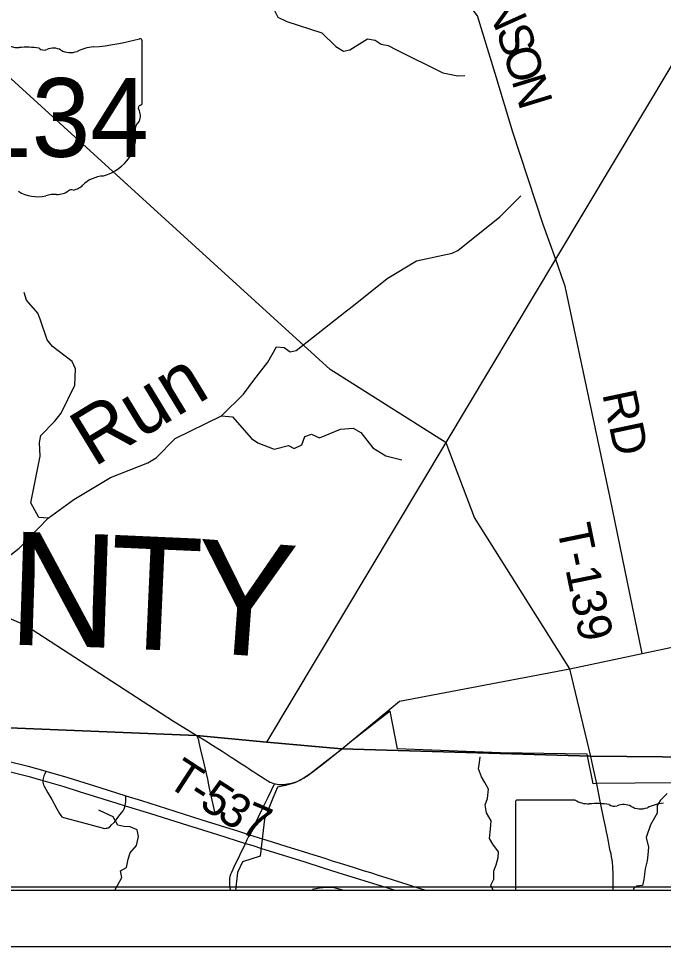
# Model space of a CAD drawing. Extents: x 0 to 34, y 0 to 22.
# Drawn here: x 4.521 to 5.601, y 14 to 15.554 of the extents above; entities that cross this region are included whole.
import ezdxf

# ---------------------------------------------------------------- set-up
doc = ezdxf.new("R2010")
doc.units = 0
for name, color, linetype in [('Default', 7, 'Continuous'), ('GM_X_City_Street', 7, 'Continuous'), ('GM_X_County_Text', 7, 'Continuous'), ('GM_X_Interchange_Ramps', 7, 'Continuous'), ('GM_X_Minor_Lake', 7, 'Continuous'), ('GM_X_Minor_River', 7, 'Continuous'), ('GM_X_Minor_River_Text', 7, 'Continuous'), ('GM_X_State_Location', 7, 'Continuous'), ('GM_X_State_Route', 7, 'Continuous'), ('GM_X_State_Shield', 7, 'Continuous'), ('GM_X_Township_Road', 7, 'Continuous'), ('GM_X_Township_Road_Text', 7, 'Continuous'), ('SH_Cut_Line', 7, 'Continuous'), ('SH_Data', 7, 'Continuous')]:
    doc.layers.add(name, color=color, linetype=linetype)

msp = doc.modelspace()

# ---------------------------------------------------------------- linework, layer by layer
at = {"layer": 'Default'}
msp.add_line((5.453, 14.2451), (5.3564, 14.2451), dxfattribs=at)
for points in [[(2.3212, 18.6531), (2.2797, 17.8302), (2.2668, 17.0936), (2.2632, 16.8811), (2.258, 16.7775), (2.1837, 15.746), (2.1, 14.637), (2.1, 14.4457), (2.4012, 14.4298), (2.4436, 14.4284), (2.5802, 14.4232), (3.783, 14.3901), (4.0144, 14.3862), (4.819, 14.3535), (4.9366, 14.3421), (5.2368, 14.8438), (5.4205, 15.1508), (5.9071, 15.964)], [(5.6182, 14.274), (5.4889, 14.273), (5.4832, 14.2724), (5.4732, 14.3218), (5.3279, 14.3242), (5.1554, 14.331), (5.1431, 14.394), (5.1265, 14.3811), (5.0756, 14.3413), (5.0632, 14.3309), (5.0346, 14.3087), (5.0087, 14.2887), (4.9974, 14.2812), (4.9836, 14.2742), (4.9678, 14.2695), (4.9546, 14.2665), (4.9467, 14.2481), (4.9329, 14.2132), (4.9257, 14.1511), (4.896, 14.1417), (4.8872, 14.1238), (4.8842, 14.0941), (5.6247, 14.0941)], [(5.3532, 14.2417), (5.3532, 14.0941), (5.6721, 14.0941)]]:
    msp.add_lwpolyline(points, dxfattribs=at)
msp.add_lwpolyline([(2.1, 14.4457), (2.1, 14.243), (2.102, 14.2411), (2.1319, 14.2168), (2.1359, 14.2103), (2.1425, 14.1753), (2.1455, 14.1482), (2.1436, 14.1288), (2.1399, 14.114), (2.1382, 14.1043), (2.1342, 14.0941), (7.3096, 14.0941), (7.3204, 14.3032), (6.8864, 14.3056), (6.7418, 14.3069), (5.4793, 14.3187), (5.0616, 14.3309), (4.9366, 14.3421), (4.819, 14.3535), (4.0144, 14.3862), (3.783, 14.3901), (2.5802, 14.4232), (2.4436, 14.4284), (2.4012, 14.4298)], close=True, dxfattribs=at)
for centre, major_axis, start_param, end_param in [((5.357, 14.2421), (0.00382, 0), 1.727492, 3.291633), ((5.476, 14.2684), (0.037, 0), 4.042888, 4.731792), ((5.4883, 14.1328), (0.133, 0), 1.404758, 1.657859), ((5.5184, 14.2432), (0.0107, 0), 3.836095, 5.185415), ((5.5341, 14.22), (0.0222, 0), 0.950623, 2.079405), ((5.61, 14.184), (0.0703, 0), 1.699012, 2.107814), ((5.5628, 14.2518), (0.0267, 0), 4.08156, 5.145723)]:
    msp.add_ellipse(centre, major_axis=major_axis, ratio=0.8, start_param=start_param, end_param=end_param, dxfattribs=at)
at = {"layer": 'GM_X_City_Street'}
msp.add_lwpolyline([(5.0132, 14.0962), (5.0156, 14.0967), (5.0247, 14.0981), (5.0364, 14.0991), (5.0438, 14.0992), (5.0486, 14.0987), (5.0558, 14.097), (5.0653, 14.0941)], dxfattribs=at)
at = {"layer": 'GM_X_Interchange_Ramps'}
msp.add_lwpolyline([(4.5664, 14.2935), (4.5651, 14.2902), (4.5632, 14.2856), (4.562, 14.2814), (4.5615, 14.278), (4.5613, 14.275), (4.5617, 14.2728), (4.5627, 14.2704), (4.5634, 14.2686), (4.5699, 14.2571), (4.5762, 14.246), (4.5851, 14.2303), (4.5894, 14.2228), (4.5914, 14.2193), (4.5932, 14.2173), (4.5958, 14.2162), (4.6256, 14.208), (4.6606, 14.1984), (4.6642, 14.1978), (4.6671, 14.1979), (4.6689, 14.1983), (4.6708, 14.1989), (4.6734, 14.2005), (4.6766, 14.2034), (4.6812, 14.2083), (4.6886, 14.2182), (4.6933, 14.224), (4.6958, 14.2273), (4.6976, 14.2306), (4.6993, 14.2356), (4.6998, 14.2386), (4.7002, 14.243), (4.7003, 14.2493), (4.7002, 14.2524)], dxfattribs=at)
at = {"layer": 'GM_X_Minor_Lake'}
msp.add_lwpolyline([(5.6072, 14.256), (5.5961, 14.2451), (5.5907, 14.2361), (5.5902, 14.2232), (5.5793, 14.2037), (5.5719, 14.1825), (5.5758, 14.1661), (5.5749, 14.1536), (5.574, 14.1434), (5.5701, 14.1298), (5.5683, 14.112), (5.5659, 14.1018), (5.5557, 14.1012), (5.5507, 14.0963), (5.5508, 14.0941)], dxfattribs=at)
at = {"layer": 'GM_X_Minor_River'}
for points in [[(4.8003, 15.6193), (4.8225, 15.6195), (4.8504, 15.6103), (4.8879, 15.5891), (4.9106, 15.5841), (4.9352, 15.5852), (4.9457, 15.5755), (4.9552, 15.5563), (4.9702, 15.5492), (5.029, 15.5299), (5.0521, 15.5071), (5.0652, 15.4993), (5.0759, 15.5017), (5.105, 15.5201), (5.1182, 15.518), (5.1283, 15.511), (5.1396, 15.5088), (5.1539, 15.5017), (5.2313, 15.4631), (5.2566, 15.4581), (5.2683, 15.4586)], [(4.5008, 14.6508), (4.5219, 14.6668), (4.5704, 14.7172), (4.6133, 14.7488), (4.6748, 14.7854), (4.7373, 14.8098), (4.7511, 14.8183), (4.7833, 14.8508), (4.8604, 14.8887), (4.8973, 14.9249), (4.9151, 14.9485), (4.9382, 14.9788), (4.9526, 15.004), (4.9655, 15.0031), (4.9756, 14.9961), (4.9855, 14.9978), (5.0698, 15.0647), (5.082, 15.0736), (5.1383, 15.1186), (5.1876, 15.1485), (5.2473, 15.1612), (5.2568, 15.1656), (5.327, 15.2222), (5.3619, 15.2569)], [(4.5704, 14.7172), (4.5545, 14.7186), (4.5412, 14.7431), (4.557, 14.821), (4.5558, 14.8438), (4.5582, 14.8559), (4.5809, 14.8794), (4.5921, 14.8929), (4.6147, 14.94), (4.6159, 14.9676), (4.6104, 14.9798), (4.5777, 15.0046), (4.5684, 15.0162), (4.5567, 15.0508), (4.5531, 15.0608), (4.534, 15.0823), (4.5301, 15.0952)], [(4.8604, 14.8887), (4.879, 14.8872), (4.9107, 14.8507), (4.9216, 14.8433), (4.9491, 14.8326), (4.9727, 14.8391), (4.9825, 14.834), (4.9954, 14.8402), (5.0005, 14.8538), (5.0112, 14.8582), (5.0248, 14.8519), (5.0598, 14.8665), (5.0814, 14.868), (5.0938, 14.8606), (5.114, 14.8353), (5.1361, 14.8216), (5.1629, 14.8151)], [(5.3159, 14.0941), (5.3121, 14.1024), (5.3168, 14.1125), (5.3166, 14.1266), (5.3209, 14.1367), (5.3241, 14.1492), (5.3246, 14.1587), (5.3153, 14.1714), (5.3094, 14.1809), (5.3115, 14.1965), (5.3124, 14.2105), (5.3047, 14.2235), (5.3026, 14.2372), (5.3061, 14.2478), (5.3078, 14.2633), (5.3019, 14.2748), (5.2964, 14.2843), (5.2913, 14.2977), (5.2929, 14.3079), (5.2938, 14.3174)], [(4.6822, 14.0941), (4.6862, 14.1022), (4.6936, 14.1157), (4.6914, 14.1264), (4.7017, 14.1323), (4.7045, 14.1459), (4.7077, 14.1565), (4.7184, 14.1688), (4.7217, 14.184), (4.7195, 14.1954), (4.7075, 14.2005), (4.6973, 14.2006), (4.6871, 14.2031), (4.6794, 14.2172), (4.6659, 14.2231), (4.655, 14.2282)]]:
    msp.add_lwpolyline(points, dxfattribs=at)
at = {"layer": 'GM_X_State_Route'}
msp.add_line((5.4796, 14.3182), (5.4443, 14.4648), dxfattribs=at)
for points in [[(5.4443, 14.4648), (5.2846, 14.7184), (5.2371, 14.8433), (5.0427, 14.9665), (4.4202, 15.5326), (4.3908, 15.5621)], [(5.4892, 14.2723), (5.4829, 14.3022), (5.4796, 14.3182)], [(4.4643, 14.3031), (4.5384, 14.2845), (4.5575, 14.2792), (4.5615, 14.278), (4.5963, 14.2678), (4.6224, 14.2597), (4.6852, 14.2399), (4.6993, 14.2356), (4.7398, 14.2232), (4.7949, 14.2057), (4.8542, 14.1872), (4.9008, 14.1726), (4.9129, 14.1688), (4.9275, 14.1641)], [(4.5025, 14.3105), (4.5368, 14.3017), (4.5649, 14.2939), (4.5664, 14.2935), (4.6031, 14.2827), (4.6571, 14.266), (4.7002, 14.2524), (4.7264, 14.2442), (4.7827, 14.2265), (4.8277, 14.2123), (4.8894, 14.1929), (4.9077, 14.1871), (4.9294, 14.1802)], [(5.5109, 14.1655), (5.5087, 14.176), (5.5071, 14.1846), (5.5056, 14.1919), (5.5037, 14.2009), (5.5012, 14.213), (5.4956, 14.2403), (5.4892, 14.2723)], [(4.9294, 14.1802), (4.9453, 14.1751), (4.9578, 14.1711), (4.9702, 14.1673), (4.9827, 14.1634), (4.9958, 14.1594), (5.0082, 14.1555), (5.0207, 14.1517), (5.0337, 14.1476), (5.0462, 14.1436), (5.0592, 14.1395), (5.0722, 14.1354), (5.0847, 14.1315), (5.0978, 14.1274), (5.1102, 14.1236), (5.1233, 14.1196), (5.1357, 14.1157), (5.1481, 14.1116), (5.1605, 14.1076), (5.173, 14.1036), (5.1848, 14.0999), (5.1967, 14.0961), (5.203, 14.0941)], [(4.9275, 14.1641), (4.9985, 14.142), (5.0311, 14.1317), (5.0553, 14.1239), (5.1444, 14.0963), (5.1512, 14.0941)], [(5.5167, 14.0941), (5.5167, 14.0958), (5.5168, 14.1009), (5.5168, 14.1064), (5.5168, 14.1141), (5.5166, 14.1206), (5.5166, 14.1252), (5.5163, 14.1291), (5.516, 14.1347), (5.5155, 14.1402), (5.5149, 14.1448), (5.5141, 14.15), (5.5132, 14.1549), (5.512, 14.1601), (5.5109, 14.1655)]]:
    msp.add_lwpolyline(points, dxfattribs=at)
at = {"layer": 'GM_X_State_Shield'}
for q in [(4.7276, 15.5168), (4.7276, 15.4121)]:
    msp.add_line((4.7276, 15.4121), q, dxfattribs=at)
for centre, major_axis, start_param, end_param in [((4.5208, 15.535), (0.037, 0), 4.042523, 4.731795), ((4.6102, 15.7846), (0.3495, 0), 4.814394, 5.042369), ((4.724, 15.5172), (0.00367, 0), 6.141152, 7.989035), ((4.5331, 15.3995), (0.133, 0), 1.404758, 1.657858), ((4.5633, 15.5098), (0.0107, 0), 3.836095, 5.185415), ((4.5789, 15.4867), (0.0222, 0), 0.950623, 2.079405), ((4.6076, 15.5184), (0.0267, 0), 4.081561, 5.145723), ((4.6548, 15.4507), (0.0703, 0), 1.699011, 2.107814), ((4.7268, 15.4044), (0.00568, 0), 1.883978, 3.671073), ((4.6907, 15.3912), (0.0341, 0), 5.934695, 6.695948), ((4.7237, 15.4117), (0.00393, 0), 5.05454, 6.418171), ((4.7408, 15.3683), (0.0248, 0), 2.387724, 3.262537), ((4.6298, 15.355), (0.0874, 0), 5.101752, 6.440018), ((4.6667, 15.2521), (0.0479, 0), 1.647645, 2.488434), ((4.5524, 15.2957), (0.0501, 0), 4.026481, 4.996735), ((4.5851, 15.2807), (0.0267, 0), 4.691044, 5.507374), ((4.6092, 15.2613), (0.00752, 0), 1.147584, 2.315152), ((4.606, 15.2888), (0.0282, 0), 4.937069, 5.64225), ((4.5814, 15.2265), (0.0412, 0), 1.495662, 1.94098)]:
    msp.add_ellipse(centre, major_axis=major_axis, ratio=0.8, start_param=start_param, end_param=end_param, dxfattribs=at)
at = {"layer": 'GM_X_Township_Road'}
msp.add_line((4.8496, 14.2252), (4.8453, 14.2447), dxfattribs=at)
for points in [[(5.4349, 15.1105), (5.4207, 15.1503), (5.3997, 15.2091), (5.3489, 15.3639), (5.3191, 15.462), (5.2897, 15.5586), (5.2503, 15.6106), (5.1765, 15.71), (5.1695, 15.7226), (5.1638, 15.7406), (5.149, 15.7629), (5.0896, 15.8198)], [(5.5651, 14.4908), (5.512, 14.7512), (5.4366, 15.1059), (5.4349, 15.1105)], [(3.7273, 14.9544), (3.9731, 14.7245), (4.0329, 14.6961), (4.2259, 14.6215), (4.436, 14.5692), (4.5009, 14.5517), (4.5325, 14.5378), (4.78, 14.3773), (4.8192, 14.353)], [(5.0618, 14.3304), (5.1587, 14.4108), (5.4443, 14.4648), (5.5651, 14.4908), (6.1002, 14.6039), (6.1021, 14.6044)], [(4.8453, 14.2447), (4.8407, 14.2652), (4.8395, 14.2706), (4.8375, 14.2804), (4.8309, 14.3088), (4.8253, 14.3317), (4.8235, 14.3418), (4.8227, 14.3455), (4.8216, 14.3485), (4.8205, 14.3504), (4.8192, 14.353)], [(4.8192, 14.353), (4.8344, 14.3442), (4.8455, 14.3373), (4.8616, 14.3268), (4.8767, 14.3171), (4.8841, 14.3124), (4.8882, 14.3097), (4.894, 14.306), (4.8997, 14.3023), (4.9064, 14.2978), (4.9095, 14.2958), (4.9147, 14.2924), (4.9199, 14.289), (4.9261, 14.2849), (4.9303, 14.2822), (4.9337, 14.28), (4.9371, 14.2779), (4.9393, 14.2767), (4.9417, 14.2754), (4.9438, 14.2745), (4.9466, 14.2735), (4.9495, 14.2726)], [(4.9495, 14.2726), (4.9514, 14.2721), (4.9539, 14.2716), (4.9559, 14.2713), (4.9583, 14.2712), (4.9602, 14.2712), (4.9625, 14.2712), (4.9654, 14.2713), (4.9678, 14.2716), (4.9712, 14.2721), (4.9748, 14.2727), (4.9775, 14.2732), (4.9806, 14.2739), (4.9821, 14.2743), (4.9839, 14.2749), (4.9857, 14.2756), (4.9876, 14.2764), (4.9898, 14.2774), (4.9921, 14.2786), (4.9948, 14.28), (4.9971, 14.2812), (4.9993, 14.2825), (5.0015, 14.2839), (5.0038, 14.2854), (5.0056, 14.2867), (5.008, 14.2884), (5.0101, 14.29), (5.0123, 14.2916), (5.0141, 14.2929), (5.0168, 14.2951), (5.0194, 14.2971), (5.0314, 14.3065), (5.0618, 14.3304)], [(4.9077, 14.1871), (4.9107, 14.1932), (4.9228, 14.2172), (4.9306, 14.2333), (4.9393, 14.2513), (4.9495, 14.2726)], [(4.8761, 14.0941), (4.876, 14.0949), (4.8752, 14.0991), (4.8748, 14.102), (4.8745, 14.1059), (4.8744, 14.1083), (4.8745, 14.1116), (4.8747, 14.1138), (4.8752, 14.1168), (4.8758, 14.1191), (4.8765, 14.1213), (4.8778, 14.1245), (4.88, 14.1293), (4.8827, 14.1351), (4.8862, 14.1423), (4.8915, 14.1529), (4.9008, 14.1726)], [(4.9008, 14.1726), (4.9039, 14.1793), (4.9077, 14.1871)]]:
    msp.add_lwpolyline(points, dxfattribs=at)
at = {"layer": 'SH_Cut_Line'}
msp.add_lwpolyline([(2.3212, 18.6531), (2.2797, 17.8302), (2.2668, 17.0936), (2.2632, 16.8811), (2.258, 16.7775), (2.1837, 15.746), (2.1, 14.637), (2.1, 14.4457), (2.4012, 14.4298), (2.4436, 14.4284), (2.5802, 14.4232), (3.783, 14.3901), (4.0144, 14.3862), (4.819, 14.3535), (4.9366, 14.3421), (5.0616, 14.3309), (5.4793, 14.3187), (6.7418, 14.3069), (6.8864, 14.3056), (7.3204, 14.3032), (8.6074, 14.2911), (8.7041, 14.2905), (8.9, 14.2922), (8.9, 20.8941)], dxfattribs=at)
at = {"layer": 'SH_Data'}
for p, q in [((2.1, 14.1), (8.9, 14.1)), ((2, 14), (9, 14))]:
    msp.add_line(p, q, dxfattribs=at)

# ---------------------------------------------------------------- texts
at = {"layer": 'GM_X_County_Text'}
for s, rotation, p in [('N', 358.1022, (4.5019, 14.5058)), ('T', 357.4625, (4.6687, 14.5002)), ('Y', 355.836, (4.8088, 14.494))]:
    msp.add_text(s, height=0.1894, rotation=rotation, dxfattribs=at).set_placement(p)
at = {"layer": 'GM_X_Minor_River_Text'}
msp.add_text('Run', height=0.09452, rotation=31.3255, dxfattribs=at).set_placement((4.6467, 14.8018))
at = {"layer": 'GM_X_State_Location'}
for s, p in [('s', (4.5591, 15.395)), ('r', (4.5591, 15.395)), ('s', (5.5143, 14.1283)), ('r', (5.5143, 14.1283))]:
    msp.add_text(s, height=0.000189, dxfattribs=at).set_placement(p)
msp.add_text('134', height=0.000189, rotation=0, dxfattribs=at).set_placement((5.4475, 14.1146))
at = {"layer": 'GM_X_State_Shield'}
msp.add_text('134', height=0.13184, dxfattribs=at).set_placement((4.4446, 15.3224))
at = {"layer": 'GM_X_Township_Road_Text'}
for s, height, rotation, p in [('N', 0.0568, 294.1452, (5.3003, 15.5788)), ('S', 0.0568, 287.3674, (5.3201, 15.5348)), ('O', 0.0568, 286.9477, (5.3315, 15.4983)), ('N', 0.0568, 286.9718, (5.3461, 15.4504)), ('RD', 0.05682, 281.8889, (5.4983, 14.9255)), ('T-139', 0.05682, 281.5852, (5.4223, 14.702)), ('T', 0.0568, 326.9161, (4.7661, 14.2708)), ('-', 0.0568, 326.9421, (4.8018, 14.2476)), ('5', 0.0568, 327.0078, (4.8214, 14.2348)), ('3', 0.0568, 327.329, (4.851, 14.2156)), ('7', 0.0568, 336.547, (4.8893, 14.192))]:
    msp.add_text(s, height=height, rotation=rotation, dxfattribs=at).set_placement(p)

doc.saveas('drawing.dxf')
